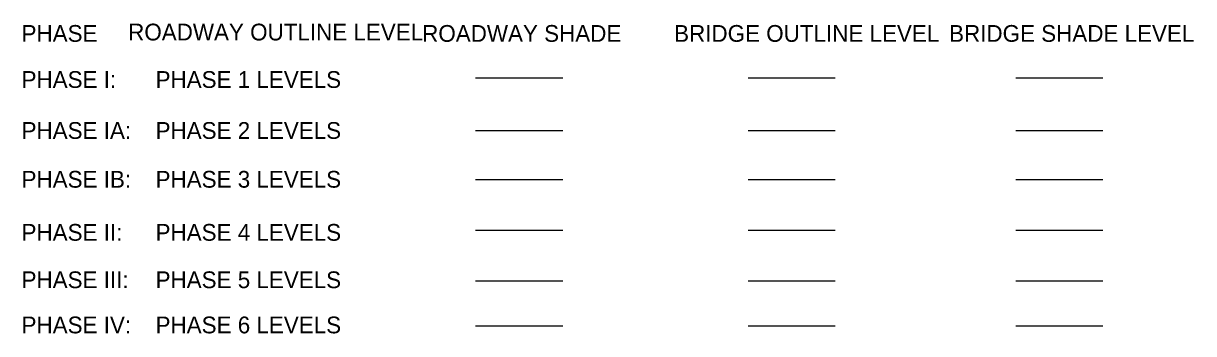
# Model space of a CAD drawing. Extents: x 2133551 to 2156187, y 140366 to 148242.
# Drawn here: x 2133551 to 2140536, y 145856 to 147707 of the extents above; entities that cross this region are included whole.
import ezdxf

# ---------------------------------------------------------------- set-up
doc = ezdxf.new("R2010")
doc.units = 0
for name, color, linetype in [('Default', 7, 'Continuous'), ('PR_Phasing_Bridge_1', 7, 'Continuous'), ('PR_Phasing_Bridge_2', 7, 'Continuous'), ('PR_Phasing_Bridge_3', 7, 'Continuous'), ('PR_Phasing_Bridge_4', 7, 'Continuous'), ('PR_Phasing_Bridge_5', 7, 'Continuous'), ('PR_Phasing_Bridge_6', 7, 'Continuous'), ('PR_Phasing_Pavement_1', 7, 'Continuous'), ('PR_Phasing_Pavement_2', 7, 'Continuous'), ('PR_Phasing_Pavement_3', 7, 'Continuous'), ('PR_Phasing_Pavement_4', 7, 'Continuous'), ('PR_Phasing_Pavement_5', 7, 'Continuous'), ('PR_Phasing_Pavement_6', 7, 'Continuous'), ('PR_Shading_Bridge_Phase_1', 7, 'Continuous'), ('PR_Shading_Bridge_Phase_2', 7, 'Continuous'), ('PR_Shading_Bridge_Phase_3', 7, 'Continuous'), ('PR_Shading_Bridge_Phase_4', 7, 'Continuous'), ('PR_Shading_Bridge_Phase_5', 7, 'Continuous'), ('PR_Shading_Bridge_Phase_6', 7, 'Continuous'), ('PR_Shading_Pavement_Phase_1', 7, 'Continuous'), ('PR_Shading_Pavement_Phase_2', 7, 'Continuous'), ('PR_Shading_Pavement_Phase_3', 7, 'Continuous'), ('PR_Shading_Pavement_Phase_4', 7, 'Continuous'), ('PR_Shading_Pavement_Phase_5', 7, 'Continuous'), ('PR_Shading_Pavement_Phase_6', 7, 'Continuous')]:
    doc.layers.add(name, color=color, linetype=linetype)

msp = doc.modelspace()

# ---------------------------------------------------------------- linework, layer by layer
at = {"layer": 'PR_Phasing_Bridge_1'}
msp.add_line((2138397.4, 147381), (2137876.7, 147381), dxfattribs=at)
at = {"layer": 'PR_Phasing_Bridge_2'}
msp.add_line((2138397.4, 147066.7), (2137876.7, 147066.7), dxfattribs=at)
at = {"layer": 'PR_Phasing_Bridge_3'}
msp.add_line((2138397.4, 146773.2), (2137876.7, 146773.2), dxfattribs=at)
at = {"layer": 'PR_Phasing_Bridge_4'}
msp.add_line((2138397.4, 146471.3), (2137876.7, 146471.3), dxfattribs=at)
at = {"layer": 'PR_Phasing_Bridge_5'}
msp.add_line((2138397.4, 146169.5), (2137876.7, 146169.5), dxfattribs=at)
at = {"layer": 'PR_Phasing_Bridge_6'}
msp.add_line((2138397.4, 145900.7), (2137876.7, 145900.7), dxfattribs=at)
at = {"layer": 'PR_Shading_Bridge_Phase_1'}
msp.add_line((2139995.4, 147381), (2139474.7, 147381), dxfattribs=at)
at = {"layer": 'PR_Shading_Bridge_Phase_2'}
msp.add_line((2139995.4, 147066.7), (2139474.7, 147066.7), dxfattribs=at)
at = {"layer": 'PR_Shading_Bridge_Phase_3'}
msp.add_line((2139995.4, 146773.2), (2139474.7, 146773.2), dxfattribs=at)
at = {"layer": 'PR_Shading_Bridge_Phase_4'}
msp.add_line((2139995.4, 146471.3), (2139474.7, 146471.3), dxfattribs=at)
at = {"layer": 'PR_Shading_Bridge_Phase_5'}
msp.add_line((2139995.4, 146169.5), (2139474.7, 146169.5), dxfattribs=at)
at = {"layer": 'PR_Shading_Bridge_Phase_6'}
msp.add_line((2139995.4, 145900.7), (2139474.7, 145900.7), dxfattribs=at)
at = {"layer": 'PR_Shading_Pavement_Phase_1'}
msp.add_line((2136770.4, 147381), (2136249.8, 147381), dxfattribs=at)
at = {"layer": 'PR_Shading_Pavement_Phase_2'}
msp.add_line((2136770.4, 147066.7), (2136249.8, 147066.7), dxfattribs=at)
at = {"layer": 'PR_Shading_Pavement_Phase_3'}
msp.add_line((2136770.4, 146773.2), (2136249.8, 146773.2), dxfattribs=at)
at = {"layer": 'PR_Shading_Pavement_Phase_4'}
msp.add_line((2136770.4, 146471.3), (2136249.8, 146471.3), dxfattribs=at)
at = {"layer": 'PR_Shading_Pavement_Phase_5'}
msp.add_line((2136770.4, 146169.5), (2136249.8, 146169.5), dxfattribs=at)
at = {"layer": 'PR_Shading_Pavement_Phase_6'}
msp.add_line((2136770.4, 145900.7), (2136249.8, 145900.7), dxfattribs=at)

# ---------------------------------------------------------------- texts
at = {"layer": 'Default'}
for s, p in [('PHASE', (2133540, 147596.9)), ('ROADWAY OUTLINE LEVEL', (2134176.3, 147605.1)), ('ROADWAY SHADE', (2135931.4, 147596.9)), ('BRIDGE OUTLINE LEVEL', (2137435.4, 147596.9)), ('BRIDGE SHADE LEVEL', (2139076.8, 147596.9))]:
    msp.add_text(s, height=100, dxfattribs=at).set_placement(p)
at = {"layer": 'PR_Phasing_Pavement_1'}
for s, p in [('PHASE I:', (2133540, 147321.9)), ('PHASE 1 LEVELS', (2134340, 147321.9))]:
    msp.add_text(s, height=100, dxfattribs=at).set_placement(p)
at = {"layer": 'PR_Phasing_Pavement_2'}
for s, p in [('PHASE IA:', (2133540, 147018)), ('PHASE 2 LEVELS', (2134340, 147018))]:
    msp.add_text(s, height=100, dxfattribs=at).set_placement(p)
at = {"layer": 'PR_Phasing_Pavement_3'}
for s, p in [('PHASE IB:', (2133540, 146726.7)), ('PHASE 3 LEVELS', (2134340, 146726.7))]:
    msp.add_text(s, height=100, dxfattribs=at).set_placement(p)
at = {"layer": 'PR_Phasing_Pavement_4'}
for s, p in [('PHASE II:', (2133540, 146410.1)), ('PHASE 4 LEVELS', (2134340, 146410.1))]:
    msp.add_text(s, height=100, dxfattribs=at).set_placement(p)
at = {"layer": 'PR_Phasing_Pavement_5'}
for s, p in [('PHASE III:', (2133540, 146127.3)), ('PHASE 5 LEVELS', (2134340, 146127.3))]:
    msp.add_text(s, height=100, dxfattribs=at).set_placement(p)
at = {"layer": 'PR_Phasing_Pavement_6'}
for s, p in [('PHASE IV:', (2133540, 145857.7)), ('PHASE 6 LEVELS', (2134340, 145857.7))]:
    msp.add_text(s, height=100, dxfattribs=at).set_placement(p)

doc.saveas('drawing.dxf')
